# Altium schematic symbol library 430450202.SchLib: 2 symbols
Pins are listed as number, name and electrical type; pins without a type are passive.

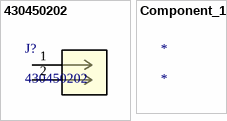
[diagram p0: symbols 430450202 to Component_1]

## 430450202
designator J?
No Description Available; Mfr_Name: Molex Connector Corporation
footprint CON_430450202_MOL
pins: 1, 2

## Component_1
designator *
